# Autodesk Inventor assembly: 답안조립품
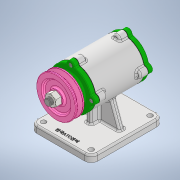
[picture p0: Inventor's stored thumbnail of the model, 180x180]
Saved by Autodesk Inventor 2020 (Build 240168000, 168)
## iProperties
Created: 2022-11
Part Number: 답안조립품
Document SubType Name: Assembly
Designer: owner
Author: owner
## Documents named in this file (12)
- C:\Users\owner\Desktop\721108V1013\답안조립품.iam
- C:\Users\owner\Desktop\721108V1013\본체.ipt
- C:\Users\owner\Desktop\721108V1013\V-벨트풀리.ipt
- C:\Users\owner\Desktop\721108V1013\개스킷.ipt
- C:\Users\owner\Desktop\721108V1013\너트 M12 x 1.25.ipt
- C:\Users\owner\Desktop\721108V1013\뒤커버.ipt
- C:\Users\owner\Desktop\721108V1013\베어링 6204.ipt
- C:\Users\owner\Desktop\721108V1013\볼트 M4 x 12.ipt
- C:\Users\owner\Desktop\721108V1013\앞커버.ipt
- C:\Users\owner\Desktop\721108V1013\오일 실.ipt
- C:\Users\owner\Desktop\721108V1013\축.ipt
- C:\Users\owner\Desktop\721108V1013\키 4 x 4.ipt
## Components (8 placed, 6 different names)
1. V-벨트풀리:1
2. 개스킷:1
3. KS B 2023 6204 - 20 x 47 x 14:1
4. KS B 2804 D D - 20 32 8:1
5. KS B 1311 (I) 4 x 4 x 12:1
6. KS B 2023 6204 - 20 x 47 x 14:2
7. 개스킷:2
8. KS B 1012 클래스 1 일반 - 미터 M12x1.25:1
